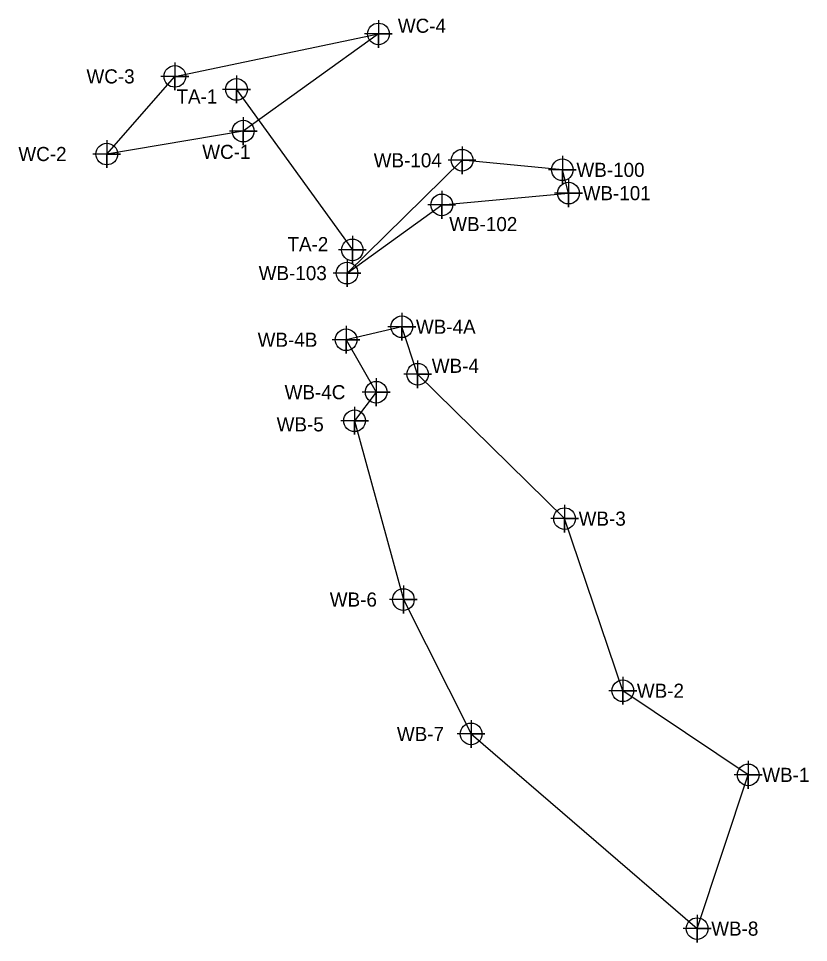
# Model space of a CAD drawing. Extents: x 1487542 to 1488992, y 498290 to 499418.
# Drawn here: x 1487956.1 to 1488126.8, y 498343.8 to 498543.3 of the extents above; entities that cross this region are included whole.
import ezdxf

# ---------------------------------------------------------------- set-up
doc = ezdxf.new("R2010")
doc.units = 0
for name, color, linetype in [('Exist Environmental Wetland Boundary', 7, 'Continuous'), ('Exist Environmental Wetland Boundary Cogo Point CELL', 7, 'Continuous'), ('Exist Environmental Wetland Boundary Text', 7, 'Continuous'), ('Exist Hydro Jurisdictional Stream or Body of Water Mitigable', 7, 'Continuous'), ('Exist Hydro Jurisdictional Stream or Body of Water Mitigable Cogo Point CELL', 7, 'Continuous'), ('Exist Hydro Jurisdictional Stream or Body of Water Mitigable Text', 7, 'Continuous')]:
    doc.layers.add(name, color=color, linetype=linetype)

msp = doc.modelspace()

# ---------------------------------------------------------------- linework, layer by layer
at = {"layer": 'Exist Environmental Wetland Boundary'}
msp.add_lwpolyline([(1487975.14, 498514.02), (1487989.85, 498530.79), (1488033.83, 498539.94), (1488004.63, 498518.96)], close=True, dxfattribs=at)
for points in [[(1488027.05, 498488.31), (1488047.52, 498503.04), (1488074.9, 498505.57), (1488073.57, 498510.61), (1488051.91, 498512.67), (1488027.05, 498488.31), (1488027.05, 498488.31)], [(1488038.89, 498476.72), (1488026.84, 498473.92), (1488033.35, 498462.59), (1488028.68, 498456.43), (1488039.22, 498417.82), (1488053.85, 498388.8), (1488102.69, 498346.76), (1488113.73, 498379.96), (1488086.63, 498398.13), (1488074.05, 498435.29), (1488042.31, 498466.47), (1488038.89, 498476.72)]]:
    msp.add_lwpolyline(points, dxfattribs=at)
at = {"layer": 'Exist Environmental Wetland Boundary Cogo Point CELL'}
for points in [[(1488033.83, 498542.94), (1488033.83, 498536.94), (1488033.83, 498539.94), (1488036.83, 498539.94), (1488030.83, 498539.94)], [(1487989.85, 498533.79), (1487989.85, 498527.79), (1487989.85, 498530.79), (1487992.85, 498530.79), (1487986.85, 498530.79)], [(1488004.63, 498521.96), (1488004.63, 498515.96), (1488004.63, 498518.96), (1488007.63, 498518.96), (1488001.63, 498518.96)], [(1487975.14, 498517.02), (1487975.14, 498511.02), (1487975.14, 498514.02), (1487978.14, 498514.02), (1487972.14, 498514.02)], [(1488051.91, 498515.67), (1488051.91, 498509.67), (1488051.91, 498512.67), (1488054.91, 498512.67), (1488048.91, 498512.67)], [(1488073.57, 498513.61), (1488073.57, 498507.61), (1488073.57, 498510.61), (1488076.57, 498510.61), (1488070.57, 498510.61)], [(1488074.9, 498508.57), (1488074.9, 498502.57), (1488074.9, 498505.57), (1488077.9, 498505.57), (1488071.9, 498505.57)], [(1488047.52, 498506.04), (1488047.52, 498500.04), (1488047.52, 498503.04), (1488050.52, 498503.04), (1488044.52, 498503.04)], [(1488027.05, 498491.31), (1488027.05, 498485.31), (1488027.05, 498488.31), (1488030.05, 498488.31), (1488024.05, 498488.31)], [(1488038.89, 498479.72), (1488038.89, 498473.72), (1488038.89, 498476.72), (1488041.89, 498476.72), (1488035.89, 498476.72)], [(1488026.84, 498476.92), (1488026.84, 498470.92), (1488026.84, 498473.92), (1488029.84, 498473.92), (1488023.84, 498473.92)], [(1488042.31, 498469.47), (1488042.31, 498463.47), (1488042.31, 498466.47), (1488045.31, 498466.47), (1488039.31, 498466.47)], [(1488033.35, 498465.59), (1488033.35, 498459.59), (1488033.35, 498462.59), (1488036.35, 498462.59), (1488030.35, 498462.59)], [(1488028.68, 498459.43), (1488028.68, 498453.43), (1488028.68, 498456.43), (1488031.68, 498456.43), (1488025.68, 498456.43)], [(1488074.05, 498438.29), (1488074.05, 498432.29), (1488074.05, 498435.29), (1488077.05, 498435.29), (1488071.05, 498435.29)], [(1488039.22, 498420.82), (1488039.22, 498414.82), (1488039.22, 498417.82), (1488042.22, 498417.82), (1488036.22, 498417.82)], [(1488086.63, 498401.13), (1488086.63, 498395.13), (1488086.63, 498398.13), (1488089.63, 498398.13), (1488083.63, 498398.13)], [(1488053.85, 498391.8), (1488053.85, 498385.8), (1488053.85, 498388.8), (1488056.85, 498388.8), (1488050.85, 498388.8)], [(1488113.73, 498382.96), (1488113.73, 498376.96), (1488113.73, 498379.96), (1488116.73, 498379.96), (1488110.73, 498379.96)], [(1488102.69, 498349.76), (1488102.69, 498343.76), (1488102.69, 498346.76), (1488105.69, 498346.76), (1488099.69, 498346.76)]]:
    msp.add_lwpolyline(points, dxfattribs=at)
for centre in [(1488033.83, 498539.94), (1487989.85, 498530.79), (1488004.63, 498518.96), (1487975.14, 498514.02), (1488051.91, 498512.67), (1488073.57, 498510.61), (1488074.9, 498505.57), (1488047.52, 498503.04), (1488027.05, 498488.31), (1488038.89, 498476.72), (1488026.84, 498473.92), (1488042.31, 498466.47), (1488033.35, 498462.59), (1488028.68, 498456.43), (1488074.05, 498435.29), (1488039.22, 498417.82), (1488086.63, 498398.13), (1488053.85, 498388.8), (1488113.73, 498379.96), (1488102.69, 498346.76)]:
    msp.add_circle(centre, 2.34, dxfattribs=at)
at = {"layer": 'Exist Hydro Jurisdictional Stream or Body of Water Mitigable'}
msp.add_line((1488003.17, 498527.97), (1488028.2, 498493.32), dxfattribs=at)
at = {"layer": 'Exist Hydro Jurisdictional Stream or Body of Water Mitigable Cogo Point CELL'}
for points in [[(1488003.17, 498530.97), (1488003.17, 498524.97), (1488003.17, 498527.97), (1488006.17, 498527.97), (1488000.17, 498527.97)], [(1488028.2, 498496.32), (1488028.2, 498490.32), (1488028.2, 498493.32), (1488031.2, 498493.32), (1488025.2, 498493.32)]]:
    msp.add_lwpolyline(points, dxfattribs=at)
for centre in [(1488003.17, 498527.97), (1488028.2, 498493.32)]:
    msp.add_circle(centre, 2.34, dxfattribs=at)

# ---------------------------------------------------------------- texts
at = {"layer": 'Exist Environmental Wetland Boundary Text'}
for s, p in [('WC-4', (1488038.03, 498540.19)), ('WC-3', (1487970.75, 498529.26)), ('WC-2', (1487956.04, 498512.5)), ('WC-1', (1487995.77, 498512.96)), ('WB-104', (1488032.81, 498511.14)), ('WB-100', (1488076.62, 498509.08)), ('WB-101', (1488077.95, 498504.05)), ('WB-102', (1488049.13, 498497.37)), ('WB-103', (1488007.96, 498486.79)), ('WB-4A', (1488041.94, 498475.2)), ('WB-4B', (1488007.74, 498472.4)), ('WB-4', (1488045.36, 498466.77)), ('WB-4C', (1488013.56, 498461.07)), ('WB-5', (1488011.84, 498454.13)), ('WB-3', (1488077.09, 498433.77)), ('WB-6', (1488023.32, 498416.3)), ('WB-2', (1488089.67, 498396.61)), ('WB-7', (1488037.82, 498387.27)), ('WB-1', (1488116.77, 498378.44)), ('WB-8', (1488105.74, 498345.24))]:
    msp.add_text(s, height=3.047, dxfattribs=at).set_placement(p)
at = {"layer": 'Exist Hydro Jurisdictional Stream or Body of Water Mitigable Text'}
for s, p in [('TA-1', (1487990.2, 498524.92)), ('TA-2', (1488014.18, 498493.04))]:
    msp.add_text(s, height=3.047, dxfattribs=at).set_placement(p)

doc.saveas('drawing.dxf')
